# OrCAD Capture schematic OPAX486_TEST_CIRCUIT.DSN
size A; title: OPAx486 48V, Zero-Drift, Low-Noise, Low-Power; rev: 1.0; note: Datasheet: SLVSL42A - FEB 2026   EVM: N/A
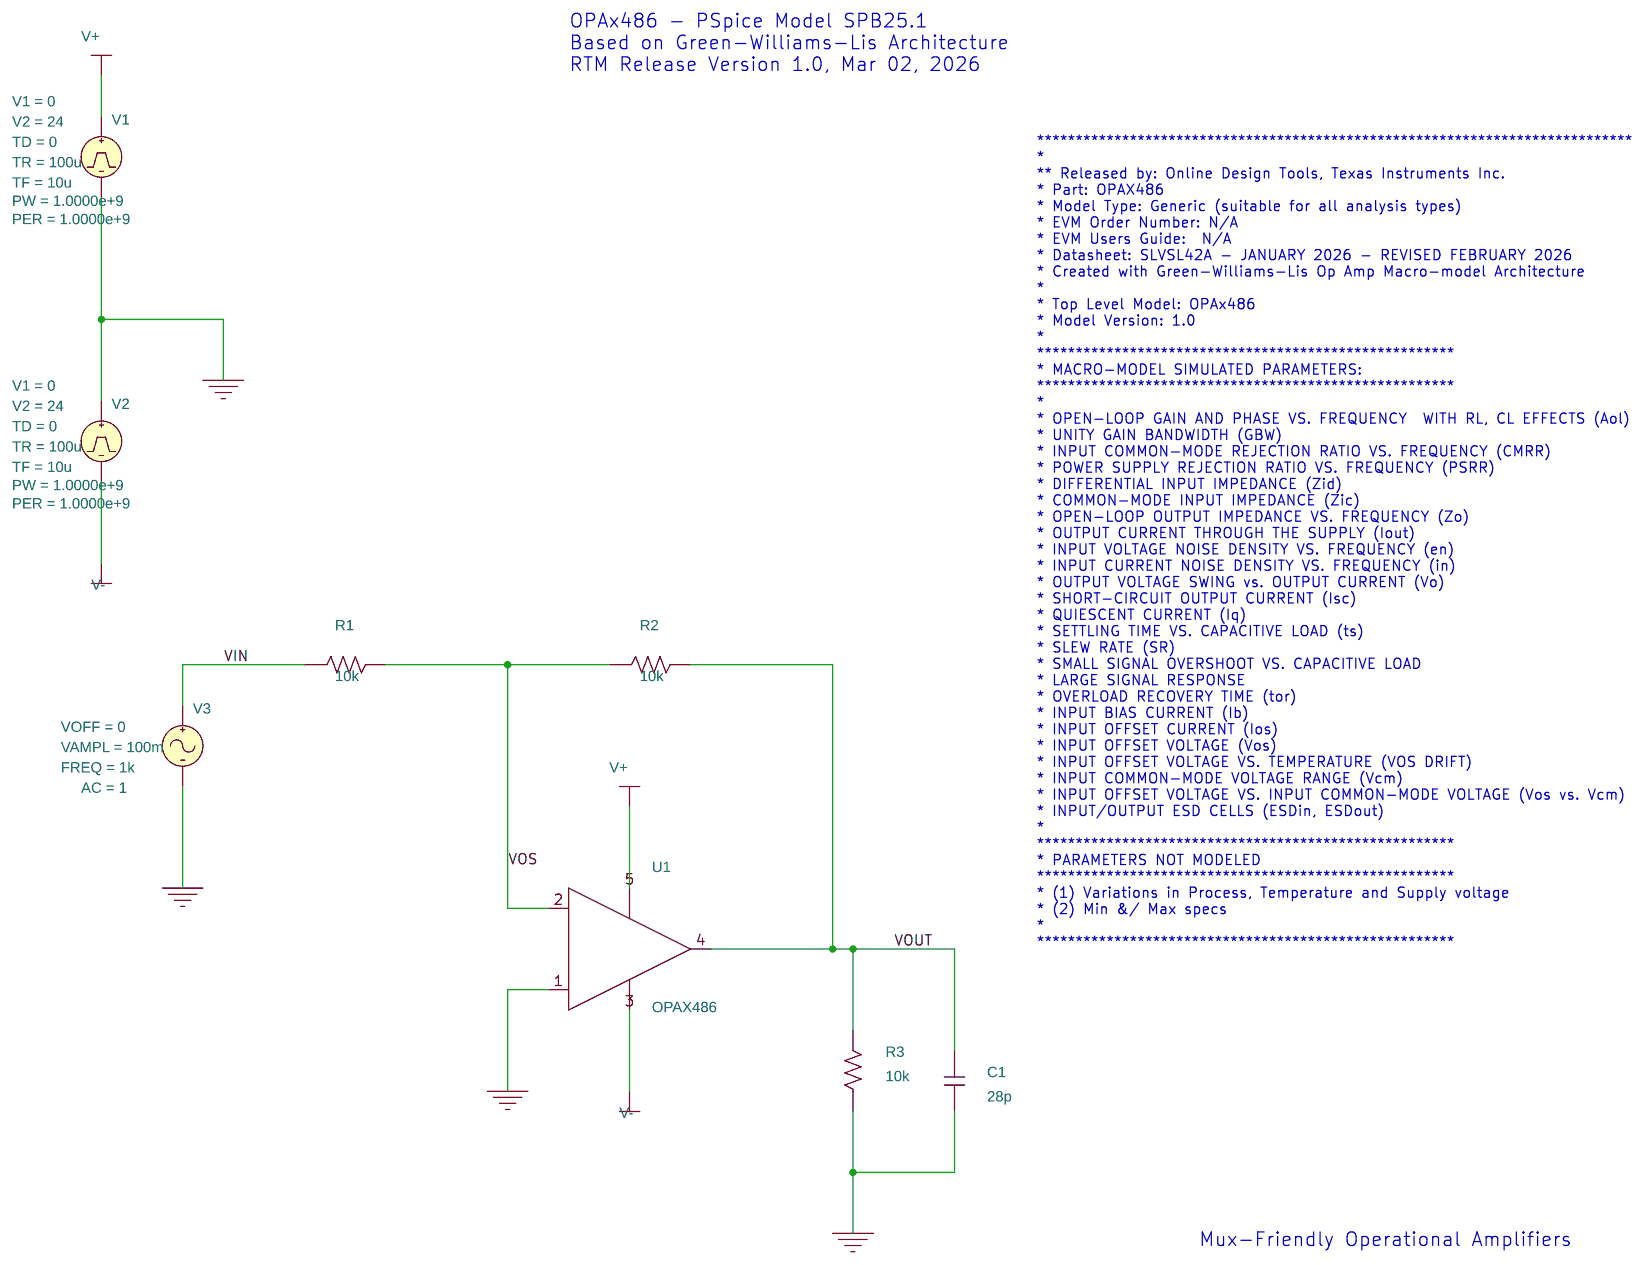
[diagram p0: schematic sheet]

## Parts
C1  28p  [cap196]
R1  10k  [AXRC05]
R2  10k  [AXRC05]
R3  10k  [AXRC05]
U1  OPAX486
V1  VPULSE
V2  VPULSE
V3  VSIN

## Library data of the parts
C1 = C
R1-R3 = R
U1 = OPAX486
V1 V2 = VPULSE: AC: 0; AppProp: Pulse$Voltage$0$-1; DC: 24; PER: 1.0000e+9; PW: 1.0000e+9; TD: 0; TF: 10u; TR: 100u; V1: 0; V2: 24
V3 = VSIN: AC: 1; AppProp: Sine$Voltage$0$-1; DC: 0; FREQ: 1k; TD: 500u; VAMPL: 100m; VOFF: 0

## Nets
VIN: R1.1 V3.1(+)
0: C1.1 R3.1 U1.1(+) V1.2(-) V2.1(+) V3.2(-)
V+: U1.5(V+) V1.1(+)
V-: U1.3(V-) V2.2(-)
VOS: R1.2 R2.1 U1.2(-)
VOUT: C1.2 R2.2 R3.2 U1.4(OUT)

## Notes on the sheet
- OPAx486 - PSpice Model SPB25.1
  Based on Green-Williams-Lis Architecture
  RTM Release Version 1.0, Mar 02, 2026
- *****************************************************************************
  *
  ** Released by: Online Design Tools, Texas Instruments Inc.
  * Part: OPAX486
  * Model Type: Generic (suitable for all analysis types)
  * EVM Order Number: N/A
  * EVM Users Guide:  N/A
  * Datasheet: SLVSL42A - JANUARY 2026 - REVISED FEBRUARY 2026
  * Created with Green-Williams-Lis Op Amp Macro-model Architecture
  *
  * Top Level Model: OPAx486
  * Model Version: 1.0
  *
  ******************************************************
  * MACRO-MODEL SIMULATED PARAMETERS:
  ******************************************************
  *
  * OPEN-LOOP GAIN AND PHASE VS. FREQUENCY  WITH RL, CL EFFECTS (Aol)
  * UNITY GAIN BANDWIDTH (GBW)
  * INPUT COMMON-MODE REJECTION RATIO VS. FREQUENCY (CMRR)
  * POWER SUPPLY REJECTION RATIO VS. FREQUENCY (PSRR)
  * DIFFERENTIAL INPUT IMPEDANCE (Zid)
  * COMMON-MODE INPUT IMPEDANCE (Zic)
  * OPEN-LOOP OUTPUT IMPEDANCE VS. FREQUENCY (Zo)
  * OUTPUT CURRENT THROUGH THE SUPPLY (Iout)
  * INPUT VOLTAGE NOISE DENSITY VS. FREQUENCY (en)
  * INPUT CURRENT NOISE DENSITY VS. FREQUENCY (in)
  * OUTPUT VOLTAGE SWING vs. OUTPUT CURRENT (Vo)
  * SHORT-CIRCUIT OUTPUT CURRENT (Isc)
  * QUIESCENT CURRENT (Iq)
  * SETTLING TIME VS. CAPACITIVE LOAD (ts)
  * SLEW RATE (SR)
  * SMALL SIGNAL OVERSHOOT VS. CAPACITIVE LOAD
  * LARGE SIGNAL RESPONSE
  * OVERLOAD RECOVERY TIME (tor)
  * INPUT BIAS CURRENT (Ib)
  * INPUT OFFSET CURRENT (Ios)
  * INPUT OFFSET VOLTAGE (Vos)
  * INPUT OFFSET VOLTAGE VS. TEMPERATURE (VOS DRIFT)
  * INPUT COMMON-MODE VOLTAGE RANGE (Vcm)
  * INPUT OFFSET VOLTAGE VS. INPUT COMMON-MODE VOLTAGE (Vos vs. Vcm)
  * INPUT/OUTPUT ESD CELLS (ESDin, ESDout)
  *
  ******************************************************
  * PARAMETERS NOT MODELED
  ******************************************************
  * (1) Variations in Process, Temperature and Supply voltage
  * (2) Min &/ Max specs
  *
  ******************************************************
- Mux-Friendly Operational Amplifiers
